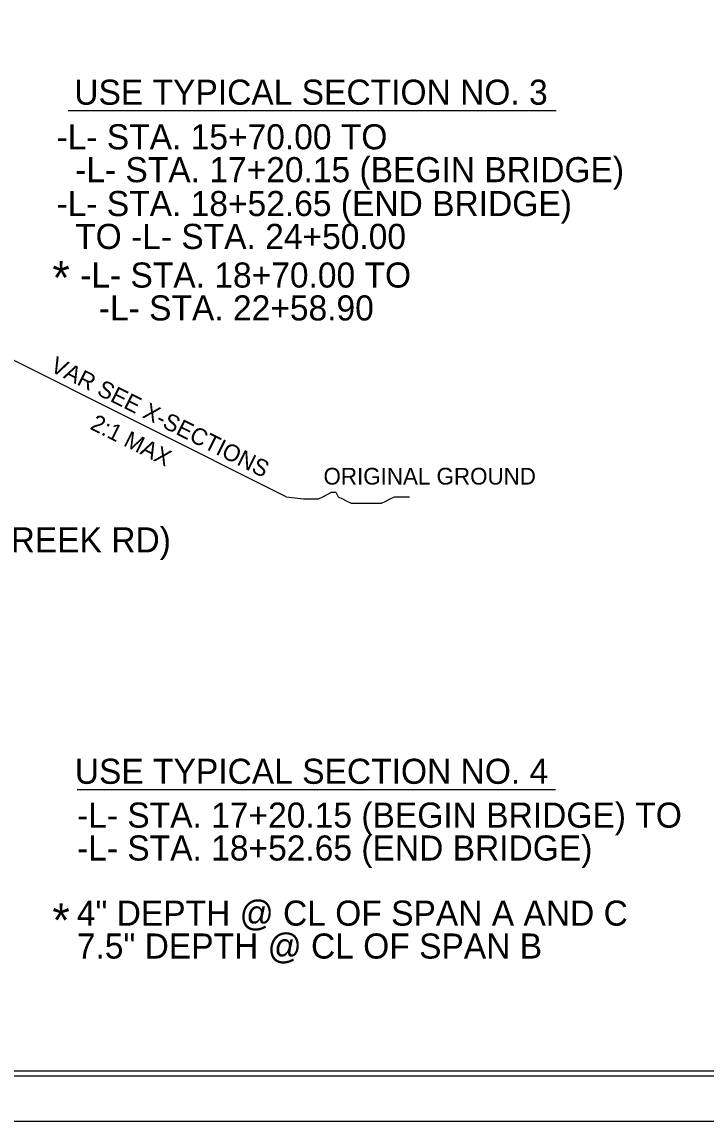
# Model space of a CAD drawing. Extents: x 573732 to 574187, y -53389 to -53257.
# Drawn here: x 573880.9 to 573921.8, y -53388.9 to -53323.2 of the extents above; entities that cross this region are included whole.
import ezdxf

# ---------------------------------------------------------------- set-up
doc = ezdxf.new("R2010")
doc.units = 0
for name, color, linetype in [('Sheet Cutting Line CELL', 7, 'Continuous'), ('Sheet Plot Border Inside CELL', 7, 'Continuous'), ('Sheet Plot Border Outside CELL', 7, 'Continuous'), ('Sheet Typical CELL', 7, 'Continuous'), ('Typical Pavement Slope Information CELL', 7, 'Continuous'), ('Typical Slope Point Local CELL', 7, 'Continuous'), ('Typical Text Centerline CELL', 7, 'Continuous'), ('Typical Text Label CELL', 7, 'Continuous')]:
    doc.layers.add(name, color=color, linetype=linetype)

msp = doc.modelspace()

# ---------------------------------------------------------------- linework, layer by layer
at = {"layer": 'Sheet Cutting Line CELL'}
msp.add_line((573782.222, -53388.948), (573984.302, -53388.948), dxfattribs=at)
at = {"layer": 'Sheet Plot Border Inside CELL'}
msp.add_lwpolyline([(573983.762, -53259.642), (573783.782, -53259.642), (573783.782, -53386.254), (573983.762, -53386.254)], close=True, dxfattribs=at)
at = {"layer": 'Sheet Plot Border Outside CELL'}
msp.add_lwpolyline([(573984.302, -53256.948), (573782.222, -53256.948), (573782.222, -53388.948), (573984.302, -53388.948)], close=True, dxfattribs=at)
at = {"layer": 'Sheet Typical CELL'}
msp.add_lwpolyline([(573982.262, -53259.948), (573802.262, -53259.948), (573802.262, -53385.948), (573982.262, -53385.948)], close=True, dxfattribs=at)
at = {"layer": 'Typical Slope Point Local CELL'}
msp.add_line((573896.67, -53351.615), (573874.171, -53340.364), dxfattribs=at)
msp.add_lwpolyline([(573896.67, -53351.615), (573897.708, -53351.744), (573897.967, -53351.744), (573898.357, -53351.744), (573898.616, -53351.744), (573898.875, -53351.615), (573899.135, -53351.485), (573899.394, -53351.354), (573899.653, -53351.354), (573899.784, -53351.615), (573900.043, -53351.744), (573900.302, -53351.874), (573900.562, -53352.003), (573900.821, -53352.003), (573901.08, -53352.003), (573901.34, -53352.003), (573901.599, -53352.003), (573901.858, -53352.003), (573902.118, -53352.003), (573902.377, -53352.003), (573902.636, -53351.874), (573902.896, -53351.744), (573903.155, -53351.615), (573903.544, -53351.615), (573903.804, -53351.615), (573904.063, -53351.615)], dxfattribs=at)
at = {"layer": 'Typical Text Label CELL'}
for p, q in [((573883.647, -53328.515), (573912.821, -53328.515)), ((573884.171, -53369.123), (573912.789, -53369.123))]:
    msp.add_line(p, q, dxfattribs=at)

# ---------------------------------------------------------------- texts
at = {"layer": 'Typical Pavement Slope Information CELL'}
for s, height, p in [('*', 2, (573882.695, -53339.522)), ('ORIGINAL GROUND', 1, (573898.91, -53350.89)), ('*', 2, (573882.695, -53377.937))]:
    msp.add_text(s, height=height, rotation=360, dxfattribs=at).set_placement(p)
for s, p in [('4" DEPTH @ CL OF SPAN A AND C', (573884.157, -53377.267)), ('7.5" DEPTH @ CL OF SPAN B', (573884.157, -53379.234))]:
    msp.add_text(s, height=1.5, dxfattribs=at).set_placement(p)
at = {"layer": 'Typical Slope Point Local CELL'}
for s, p in [('VAR SEE X-SECTIONS', (573882.506, -53344.089)), ('2:1 MAX', (573884.892, -53347.539))]:
    msp.add_text(s, height=1, rotation=333.43495, dxfattribs=at).set_placement(p)
at = {"layer": 'Typical Text Centerline CELL'}
msp.add_text('-L- (SR 1116 CEDAR CREEK RD)', height=1.5, rotation=360, dxfattribs=at).set_placement((573859.133, -53354.947))
at = {"layer": 'Typical Text Label CELL'}
for s, p in [('USE TYPICAL SECTION NO. 3', (573884.007, -53328.176)), ('USE TYPICAL SECTION NO. 4', (573884.037, -53368.785))]:
    msp.add_text(s, height=1.5, rotation=360, dxfattribs=at).set_placement(p)
for s, p in [('-L- STA. 15+70.00 TO', (573882.943, -53330.843)), ('  -L- STA. 17+20.15 (BEGIN BRIDGE)', (573882.943, -53332.809)), ('-L- STA. 18+52.65 (END BRIDGE)', (573882.943, -53334.834)), ('  TO -L- STA. 24+50.00', (573882.943, -53336.8)), ('-L- STA. 18+70.00 TO', (573884.358, -53339.11)), ('  -L- STA. 22+58.90', (573884.358, -53341.077)), ('-L- STA. 17+20.15 (BEGIN BRIDGE) TO', (573884.171, -53371.405)), ('-L- STA. 18+52.65 (END BRIDGE)', (573884.171, -53373.372))]:
    msp.add_text(s, height=1.5, dxfattribs=at).set_placement(p)

doc.saveas('drawing.dxf')
